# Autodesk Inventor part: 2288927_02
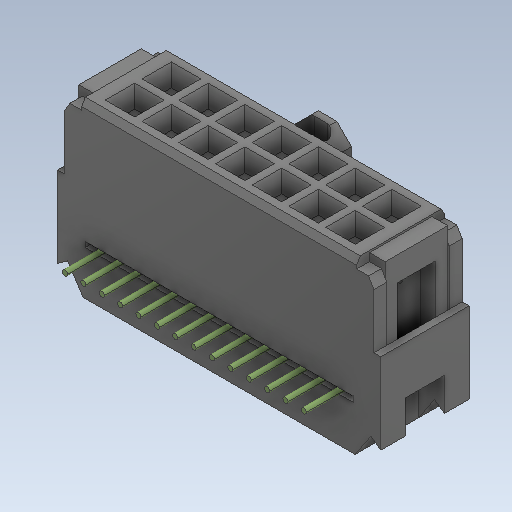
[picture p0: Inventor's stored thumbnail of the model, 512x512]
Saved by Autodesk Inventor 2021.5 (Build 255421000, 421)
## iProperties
Created: 2026-04
Part Number: 2288927_02
Checked By: TraceParts S.A.
Material: Generic
Catalog Web Link: www.traceparts.com
Document SubType Name: Modeling
Designer: TraceParts
Density: 1 g/cm^3
Appearance: Default
Company: TraceParts S.A.
Author: TraceParts
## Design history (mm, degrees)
feature "2288927_02.ipt"
body "Solid1"
